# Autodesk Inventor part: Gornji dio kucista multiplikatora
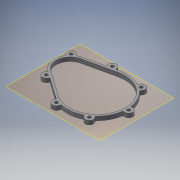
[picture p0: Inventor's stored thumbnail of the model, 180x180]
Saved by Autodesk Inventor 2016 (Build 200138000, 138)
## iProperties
Created: 2015-08
Part Number: Gornji dio kucista multiplikatora
Material: Generic
Document SubType Name: Modeling
Designer: Ugljesa
Density: 1 g/cm^3
Appearance: Default
Mass: 137.362 g
Surface Area: 628.125 cm^2
Volume: 137.362 cm^3
Author: Ugljesa
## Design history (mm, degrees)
workplane "Work Plane12"
sketch "Sketch20"
  geometry: L1 (-68.306, 46.288)-(8.188, 63.552) reference; L2 (-16.938, -61.799)-(-80.869, -16.387) reference; L3 (-83.764, -20.463)-(-82.134, -21.622) reference; L4 (-84.214, -26.277)-(-81.898, -23.016) reference; L5 (-65.592, -34.598)-(-67.909, -37.859) reference; L6 (-64.198, -34.362)-(-19.833, -65.875) reference; L7 (-11.518, -71.975)-(-12.931, -75.856) reference; L8 (5.863, -82.697)-(7.276, -78.815) reference; L9 (58.54, -72.066)-(60.909, -75.45) reference; L10 (77.292, -63.978)-(74.923, -60.595) reference; L11 (98.799, -14.73)-(102.929, -14.73) reference; L12 (102.929, 5.27)-(98.799, 5.27) reference; L13 (74.923, 51.134)-(77.292, 54.518) reference; L14 (60.909, 65.989)-(58.54, 62.606) reference; L15 (7.087, 68.43)-(-0.149, 66.797) reference; L16 (-1.344, 67.552)-(-2.225, 71.454) reference; L17 (-21.734, 67.051)-(-20.854, 63.149) reference; L18 (-21.609, 61.953)-(-69.407, 51.166) reference; L19 (-82.919, 51.059)-(-80.048, 47.949) reference; L20 (-94.742, 34.382)-(-97.613, 37.492) reference; C1 r 4 at (-90.266, 44.275) reference; C2 r 4 at (-11.98, 69.252) reference; C3 r 4 at (-76.061, -32.068) reference; C4 r 4 at (-3.534, -79.276) reference; C5 r 4 at (69.101, -69.714) reference; C6 r 4 at (102.929, -4.73) reference; C7 r 4 at (69.101, 60.253) reference; A1 r 35 centre (-60.601, 12.147) between (-68.306, 46.288) and (-80.869, -16.387) reference; A2 r 70 centre (23.599, -4.73) between (-16.938, -61.799) and (8.188, 63.552) reference; A3 r 40 centre (-60.601, 12.147) between (-94.626, 33.177) and (-83.764, -20.463) reference; A4 r 1 centre (-82.713, -22.437) between (-81.898, -23.016) and (-82.134, -21.622) reference; A5 r 10 centre (-76.061, -32.068) between (-84.214, -26.277) and (-67.909, -37.859) reference; A6 r 1 centre (-64.777, -35.177) between (-64.198, -34.362) and (-65.592, -34.598) reference; A7 r 75 centre (23.599, -4.73) between (-19.833, -65.875) and (-11.983, -70.752) reference; A8 r 1 centre (-12.458, -71.633) between (-11.518, -71.975) and (-11.983, -70.752) reference; A9 r 10 centre (-3.534, -79.276) between (-12.931, -75.856) and (5.863, -82.697) reference; A10 r 1 centre (8.216, -79.157) between (8.418, -78.178) and (7.276, -78.815) reference; A11 r 75 centre (23.599, -4.73) between (8.418, -78.178) and (57.272, -71.746) reference; A12 r 1 centre (57.721, -72.64) between (58.54, -72.066) and (57.272, -71.746) reference; A13 r 10 centre (69.101, -69.714) between (60.909, -75.45) and (77.292, -63.978) reference; A14 r 1 centre (75.742, -60.021) between (75.056, -59.293) and (74.923, -60.595) reference; A15 r 75 centre (23.599, -4.73) between (75.056, -59.293) and (97.809, -15.586) reference; A16 r 1 centre (98.799, -15.73) between (98.799, -14.73) and (97.809, -15.586) reference; A17 r 10 centre (102.929, -4.73) between (102.929, -14.73) and (102.929, 5.27) reference; A18 r 1 centre (98.799, 6.27) between (97.809, 6.125) and (98.799, 5.27) reference; A19 r 75 centre (23.599, -4.73) between (97.809, 6.125) and (75.056, 49.833) reference; A20 r 1 centre (75.742, 50.56) between (74.923, 51.134) and (75.056, 49.833) reference; A21 r 10 centre (69.101, 60.253) between (77.292, 54.518) and (60.909, 65.989) reference; A22 r 1 centre (57.721, 63.179) between (57.272, 62.286) and (58.54, 62.606) reference; A23 r 75 centre (23.599, -4.73) between (57.272, 62.286) and (7.087, 68.43) reference; A24 r 1 centre (-0.369, 67.772) between (-1.344, 67.552) and (-0.149, 66.797) reference; A25 r 10 centre (-11.98, 69.252) between (-2.225, 71.454) and (-21.734, 67.051) reference; A26 r 1 centre (-21.829, 62.929) between (-21.609, 61.953) and (-20.854, 63.149) reference; A27 r 40 centre (-60.601, 12.147) between (-69.407, 51.166) and (-78.857, 47.738) reference; A28 r 1 centre (-79.313, 48.628) between (-80.048, 47.949) and (-78.857, 47.738) reference; A29 r 10 centre (-90.266, 44.275) between (-82.919, 51.059) and (-97.613, 37.492) reference; A30 r 1 centre (-95.477, 33.703) between (-94.626, 33.177) and (-94.742, 34.382) reference; 1 further point
extrude "Extrusion18" new body sketch "Sketch20" distance "d136" = 11; taper "d137" = 0 deg
sketch "Sketch21"
  geometry: L1 (-16.938, -61.799)-(-80.869, -16.387) reference; L2 (-68.306, 46.288)-(8.188, 63.552) reference; C1 r 10 at (23.599, -4.73) reference; C2 r 11 at (23.599, -4.73); A1 r 70 centre (23.599, -4.73) between (-16.938, -61.799) and (8.188, 63.552) reference; A2 r 35 centre (-60.601, 12.147) between (-68.306, 46.288) and (-80.869, -16.387) reference; 1 further point
  constraints: 1 centre point, 1 coincident
  dimensions: "d140" = 22 diameter of C2
extrude "Extrusion20" join sketch "Sketch21" distance "d141" = 5; taper "d142" = 0 deg
fillet "Fillet28" dims "d147" = 2
fillet "Fillet29" dims "d148" = 4
body "Solid3"
node "Reference13"
node "Reference14"
